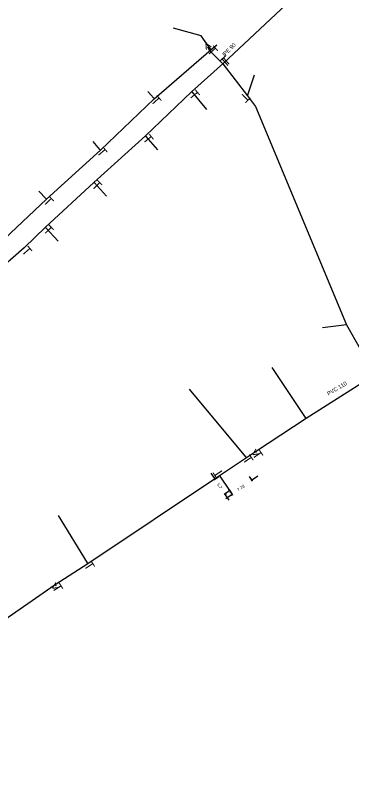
# Model space of a CAD drawing. Extents: x -634006 to -632185, y -1101085 to -1098649.
# Drawn here: x -633681.5 to -633571.4, y -1099355.5 to -1099105 of the extents above; entities that cross this region are included whole.
import ezdxf

# ---------------------------------------------------------------- set-up
doc = ezdxf.new("R2010")
doc.units = 0
for name, color, linetype in [('VP Hydrant', 7, 'Continuous'), ('VP Kótování', 7, 'Continuous'), ('VP Přípojka', 7, 'Continuous'), ('VP Zaslepení přípojky', 7, 'Continuous'), ('VP Řad', 7, 'Continuous'), ('VP Řad - popis', 7, 'Continuous'), ('VP Šoupě', 7, 'Continuous')]:
    doc.layers.add(name, color=color, linetype=linetype)

msp = doc.modelspace()

# ---------------------------------------------------------------- linework, layer by layer
at = {"layer": 'VP Kótování'}
for points in [[(-633617.51, -1099254.64), (-633616.11, -1099256.72)], [(-633614.91, -1099255.9), (-633616.32, -1099256.85)], [(-633605.03, -1099255.8), (-633604.03, -1099257.23)], [(-633602.13, -1099255.59), (-633604.18, -1099257.03)], [(-633611.72, -1099260.63), (-633613.14, -1099261.58)], [(-633611.41, -1099260.26), (-633610.4, -1099261.69)], [(-633611.53, -1099263.52), (-633612.93, -1099261.44)], [(-633612.6, -1099262.92), (-633610.55, -1099261.48)]]:
    msp.add_lwpolyline(points, dxfattribs=at)
at = {"layer": 'VP Přípojka'}
for points in [[(-633617.4, -1099116.2), (-633618.13, -1099115.38), (-633620.75, -1099111.71), (-633629.79, -1099109.15)], [(-633617.84, -1099116.58), (-633618.49, -1099115.41)], [(-633603.41, -1099124.56), (-633605.51, -1099131.05), (-633605.58, -1099131.29)], [(-633636.05, -1099132.26), (-633636.22, -1099132.08), (-633638.14, -1099129.93)], [(-633623.84, -1099129.99), (-633623.66, -1099130.16), (-633618.98, -1099135.78)], [(-633638.91, -1099144.4), (-633638.78, -1099144.61), (-633634.94, -1099148.95)], [(-633653.69, -1099149.06), (-633653.86, -1099148.88), (-633656.09, -1099146.23)], [(-633655.84, -1099159.67), (-633655.63, -1099159.81), (-633651.69, -1099164.08)], [(-633671.3, -1099165.12), (-633671.46, -1099164.97), (-633673.83, -1099162.44)], [(-633671.62, -1099174.21), (-633671.48, -1099174.42), (-633667.52, -1099178.87)], [(-633573.15, -1099206.18), (-633581.01, -1099207.18)], [(-633586.39, -1099236.7), (-633586.54, -1099236.5), (-633597.48, -1099220.11)], [(-633605.9, -1099249.51), (-633606.04, -1099249.3), (-633624.55, -1099227.15)], [(-633602.64, -1099247.88), (-633602.83, -1099247.75), (-633602.96, -1099247.53)], [(-633611.31, -1099260.35), (-633614.49, -1099255.62), (-633614.65, -1099255.39)], [(-633657.73, -1099284.2), (-633657.91, -1099284.02), (-633667.4, -1099268.5)], [(-633668.15, -1099291.56), (-633668.29, -1099291.27), (-633668.42, -1099291.07)]]:
    msp.add_lwpolyline(points, dxfattribs=at)
at = {"layer": 'VP Řad'}
for points in [[(-633462.74, -1098992.72), (-633462.97, -1098992.76), (-633474.56, -1098995.67), (-633490.38, -1099009.08), (-633496.86, -1099015.77), (-633497.15, -1099016.08), (-633497.65, -1099016.67), (-633503.55, -1099022.12), (-633510.74, -1099028.2), (-633534.16, -1099049.11), (-633541.45, -1099055.72), (-633547.31, -1099061.8), (-633550.72, -1099065.74), (-633560.48, -1099074.01), (-633566.79, -1099080.1), (-633574.16, -1099083.83), (-633613.39, -1099120.61), (-633623.84, -1099129.99), (-633638.91, -1099144.4), (-633655.84, -1099159.67), (-633671.62, -1099174.21), (-633678.6, -1099180.99), (-633688.6, -1099189.7)], [(-633636.05, -1099132.26), (-633617.4, -1099116.2), (-633615.58, -1099114.64)], [(-633617.84, -1099116.58), (-633613.61, -1099120.81)], [(-633613.61, -1099120.81), (-633605.58, -1099131.29), (-633602.91, -1099134.76), (-633573.15, -1099206.18), (-633564.21, -1099221.87), (-633563.96, -1099222.35)], [(-633794.94, -1099259.57), (-633773.2, -1099253.39), (-633760.94, -1099248.49), (-633745.81, -1099236.02), (-633729.35, -1099219.6), (-633729.04, -1099219.32), (-633719.58, -1099210.56), (-633702.99, -1099194.96), (-633687.16, -1099179.89), (-633671.29, -1099165.15), (-633653.69, -1099149.06), (-633636.05, -1099132.26)], [(-633820.59, -1099355.5), (-633798.04, -1099352.76), (-633785.58, -1099350.46), (-633774.78, -1099347.64), (-633758.64, -1099343.11), (-633747.89, -1099339.05), (-633724.2, -1099327.44), (-633709.99, -1099319), (-633686.36, -1099303.46), (-633668.43, -1099291.07), (-633657.73, -1099284.2), (-633614.65, -1099255.39), (-633605.9, -1099249.51), (-633602.96, -1099247.53), (-633586.39, -1099236.7), (-633564.88, -1099223.02), (-633563.96, -1099222.35)]]:
    msp.add_lwpolyline(points, dxfattribs=at)

# ---------------------------------------------------------------- texts
at = {"layer": 'VP Hydrant'}
for rotation, p in [(119.2294, (-633616.82, -1099115.33)), (213.9757, (-633602.86, -1099246.22)), (212.739, (-633668.33, -1099289.89))]:
    msp.add_text('>', height=3, rotation=rotation, dxfattribs=at).set_placement(p)
at = {"layer": 'VP Kótování'}
for s, rotation, p in [('z', 303.9575, (-633616.81, -1099256.58)), ('5,7', 303.9575, (-633615.65, -1099258.31)), ('7,78', 34.9696, (-633608.51, -1099260.67)), ('z', 214.9696, (-633604.05, -1099256.33)), ('z', 123.9575, (-633612.24, -1099261.58)), ('z', 34.9696, (-633610.67, -1099262.18))]:
    msp.add_text(s, height=1, rotation=rotation, dxfattribs=at).set_placement(p)
at = {"layer": 'VP Zaslepení přípojky'}
msp.add_text('[', height=1, rotation=33.9575, dxfattribs=at).set_placement((-633611.44, -1099261.05))
at = {"layer": 'VP Řad - popis'}
for s, rotation, p in [('lPE 90', 44.9661, (-633612.99, -1099118.55)), ('PVC 110', 30.7052, (-633579.02, -1099229.37))]:
    msp.add_text(s, height=1.3, rotation=rotation, dxfattribs=at).set_placement(p)
at = {"layer": 'VP Šoupě'}
for rotation, p in [(311.7953, (-633618.95, -1099116.72)), (41.0041, (-633612.48, -1099121.8)), (41.9005, (-633612.85, -1099122.24)), (309.7785, (-633624.87, -1099131.05)), (223.4292, (-633606.47, -1099129.9)), (311.7953, (-633637.4, -1099133.01)), (309.0103, (-633640, -1099145.48)), (310.0729, (-633655.07, -1099149.77)), (315.2419, (-633656.75, -1099160.81)), (313.1154, (-633672.62, -1099165.93)), (314.1509, (-633672.62, -1099175.4)), (311.0541, (-633679.68, -1099182.14)), (304.2517, (-633607.33, -1099250.07)), (303.9757, (-633604.13, -1099248.51)), (123.7922, (-633613.19, -1099254.87)), (303.5481, (-633659.21, -1099284.77)), (302.739, (-633669.6, -1099292))]:
    msp.add_text('T', height=3, rotation=rotation, dxfattribs=at).set_placement(p)

doc.saveas('drawing.dxf')
